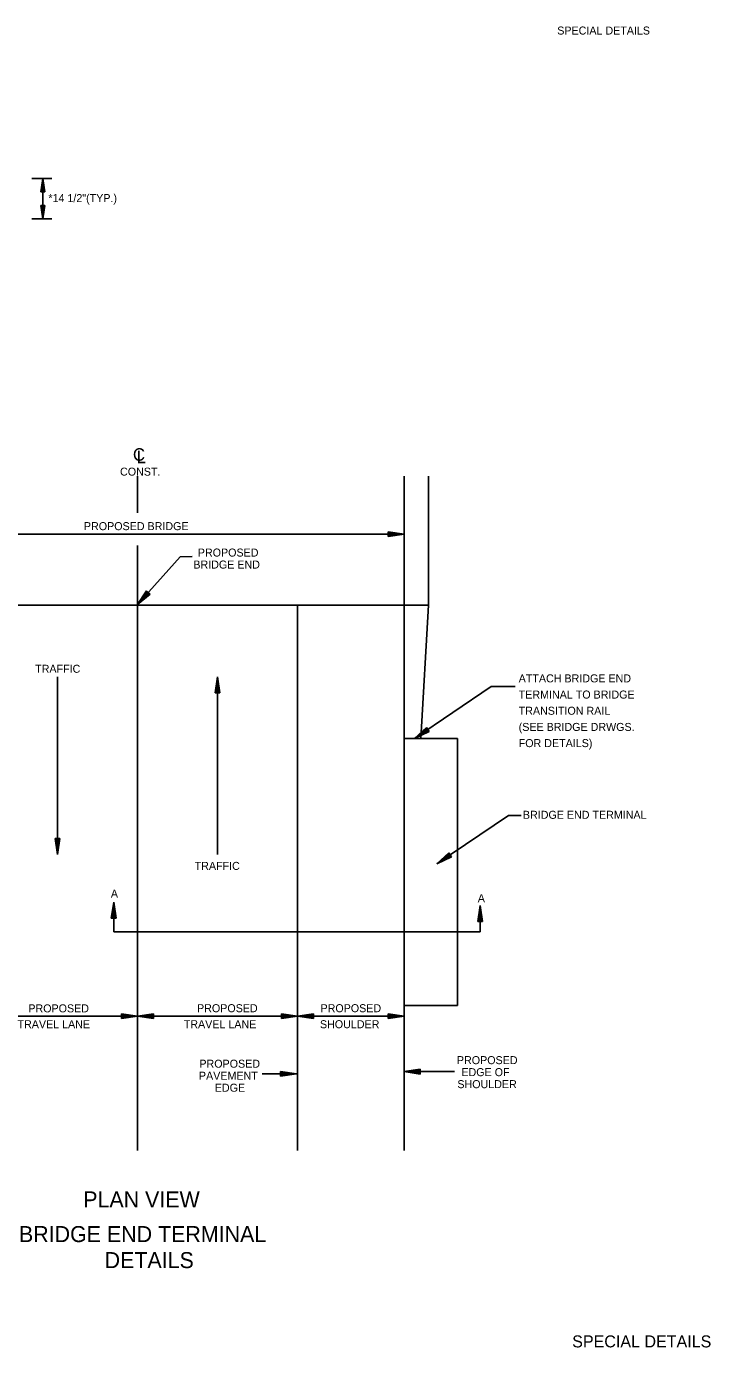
# Model space of a CAD drawing. Extents: x 1373918 to 1374069, y 381000 to 381245.
# Drawn here: x 1374017.6 to 1374068.9, y 381000 to 381099 of the extents above; entities that cross this region are included whole.
import ezdxf

# ---------------------------------------------------------------- set-up
doc = ezdxf.new("R2010")
doc.units = 0
for name, color, linetype in [('Default', 7, 'Continuous'), ('G-ANNO-TEXT', 7, 'Continuous'), ('R_Draft', 7, 'Continuous')]:
    doc.layers.add(name, color=color, linetype=linetype)

msp = doc.modelspace()

# ---------------------------------------------------------------- linework, layer by layer
at = {"layer": 'Default'}
for p, q in [((1374018.003, 381087.644), (1374019.497, 381087.644)), ((1374018.671, 381086.645), (1374018.821, 381087.645)), ((1374018.696, 381086.645), (1374018.821, 381087.48)), ((1374018.724, 381086.645), (1374018.821, 381087.307)), ((1374018.749, 381086.645), (1374018.821, 381087.14)), ((1374018.774, 381086.645), (1374018.821, 381086.97)), ((1374018.971, 381086.645), (1374018.821, 381087.645)), ((1374018.946, 381086.645), (1374018.821, 381087.48)), ((1374018.921, 381086.645), (1374018.821, 381087.307)), ((1374018.896, 381086.645), (1374018.821, 381087.14)), ((1374018.871, 381086.645), (1374018.821, 381086.97)), ((1374018.822, 381087.644), (1374018.822, 381084.623)), ((1374018.671, 381086.645), (1374018.971, 381086.645)), ((1374018.799, 381086.645), (1374018.821, 381086.805)), ((1374018.846, 381086.645), (1374018.821, 381086.805)), ((1374018.671, 381085.622), (1374018.821, 381084.622)), ((1374018.971, 381085.622), (1374018.671, 381085.622)), ((1374018.696, 381085.622), (1374018.821, 381084.79)), ((1374018.724, 381085.622), (1374018.821, 381084.962)), ((1374018.749, 381085.622), (1374018.821, 381085.127)), ((1374018.774, 381085.622), (1374018.821, 381085.297)), ((1374018.799, 381085.622), (1374018.821, 381085.465)), ((1374018.971, 381085.622), (1374018.821, 381084.622)), ((1374018.871, 381085.622), (1374018.821, 381085.297)), ((1374018.921, 381085.622), (1374018.821, 381084.962)), ((1374018.946, 381085.622), (1374018.821, 381084.79)), ((1374018.896, 381085.622), (1374018.821, 381085.127)), ((1374018.846, 381085.622), (1374018.821, 381085.465)), ((1374018.003, 381084.622), (1374019.497, 381084.622)), ((1374025.924, 381065.347), (1374025.924, 381062.586)), ((1374045.924, 381065.347), (1374045.924, 381055.667)), ((1374047.757, 381065.347), (1374047.757, 381055.667)), ((1374013.007, 381060.99), (1374045.924, 381060.99)), ((1374044.724, 381061.17), (1374045.924, 381060.99)), ((1374044.724, 381061.17), (1374044.724, 381060.81)), ((1374044.724, 381061.14), (1374045.724, 381060.99)), ((1374044.724, 381061.109), (1374045.517, 381060.99)), ((1374044.724, 381061.079), (1374045.317, 381060.99)), ((1374044.724, 381061.048), (1374045.114, 381060.99)), ((1374044.724, 381061.018), (1374044.914, 381060.99)), ((1374044.724, 381060.81), (1374045.924, 381060.99)), ((1374044.724, 381060.931), (1374045.114, 381060.99)), ((1374044.724, 381060.871), (1374045.517, 381060.99)), ((1374044.724, 381060.84), (1374045.724, 381060.99)), ((1374044.724, 381060.901), (1374045.317, 381060.99)), ((1374044.724, 381060.962), (1374044.914, 381060.99)), ((1374025.924, 381060.131), (1374025.924, 381014.792)), ((1374025.936, 381055.724), (1374029.124, 381059.302)), ((1374029.124, 381059.302), (1374030.028, 381059.304)), ((1374026.6, 381056.74), (1374025.936, 381055.724)), ((1374026.869, 381056.5), (1374025.936, 381055.724)), ((1374026.622, 381056.72), (1374026.069, 381055.874)), ((1374026.846, 381056.52), (1374026.069, 381055.874)), ((1374026.645, 381056.699), (1374026.207, 381056.028)), ((1374026.823, 381056.541), (1374026.207, 381056.028)), ((1374026.668, 381056.679), (1374026.34, 381056.177)), ((1374026.801, 381056.56), (1374026.34, 381056.177)), ((1374026.69, 381056.659), (1374026.475, 381056.329)), ((1374026.778, 381056.581), (1374026.475, 381056.329)), ((1374026.869, 381056.5), (1374026.6, 381056.74)), ((1374026.713, 381056.639), (1374026.608, 381056.478)), ((1374026.755, 381056.601), (1374026.608, 381056.478)), ((1374013.338, 381055.667), (1374047.757, 381055.667)), ((1374037.924, 381055.667), (1374037.924, 381014.792)), ((1374045.924, 381055.667), (1374045.924, 381045.667)), ((1374047.174, 381045.667), (1374047.757, 381055.667)), ((1374019.924, 381050.285), (1374019.924, 381036.974)), ((1374031.744, 381049.085), (1374031.924, 381050.285)), ((1374031.774, 381049.085), (1374031.924, 381050.085)), ((1374031.805, 381049.085), (1374031.924, 381049.878)), ((1374031.835, 381049.085), (1374031.924, 381049.678)), ((1374031.866, 381049.085), (1374031.924, 381049.475)), ((1374031.924, 381050.285), (1374031.924, 381036.974)), ((1374032.104, 381049.085), (1374031.924, 381050.285)), ((1374032.074, 381049.085), (1374031.924, 381050.085)), ((1374032.043, 381049.085), (1374031.924, 381049.878)), ((1374032.013, 381049.085), (1374031.924, 381049.678)), ((1374031.983, 381049.085), (1374031.924, 381049.475)), ((1374046.706, 381045.679), (1374052.457, 381049.578)), ((1374052.457, 381049.578), (1374054.266, 381049.578)), ((1374031.744, 381049.085), (1374032.104, 381049.085)), ((1374031.896, 381049.085), (1374031.924, 381049.275)), ((1374031.952, 381049.085), (1374031.924, 381049.275)), ((1374047.598, 381046.501), (1374046.706, 381045.679)), ((1374047.615, 381046.477), (1374046.872, 381045.791)), ((1374047.632, 381046.451), (1374047.043, 381045.907)), ((1374047.649, 381046.426), (1374047.208, 381046.019)), ((1374047.666, 381046.401), (1374047.376, 381046.134)), ((1374047.683, 381046.376), (1374047.542, 381046.246)), ((1374047.8, 381046.203), (1374047.598, 381046.501)), ((1374045.921, 381045.667), (1374045.921, 381025.667)), ((1374045.924, 381045.884), (1374045.924, 381014.792)), ((1374045.924, 381045.667), (1374049.928, 381045.667)), ((1374047.8, 381046.203), (1374046.706, 381045.679)), ((1374047.783, 381046.228), (1374046.872, 381045.791)), ((1374047.766, 381046.254), (1374047.043, 381045.907)), ((1374047.749, 381046.278), (1374047.208, 381046.019)), ((1374047.732, 381046.304), (1374047.376, 381046.134)), ((1374047.715, 381046.329), (1374047.542, 381046.246)), ((1374049.928, 381045.667), (1374049.928, 381025.667)), ((1374048.389, 381036.283), (1374053.75, 381039.902)), ((1374053.75, 381039.902), (1374054.696, 381039.909)), ((1374019.744, 381038.174), (1374019.924, 381036.974)), ((1374020.104, 381038.174), (1374019.744, 381038.174)), ((1374019.774, 381038.174), (1374019.924, 381037.174)), ((1374019.805, 381038.174), (1374019.924, 381037.381)), ((1374019.835, 381038.174), (1374019.924, 381037.581)), ((1374019.865, 381038.174), (1374019.924, 381037.784)), ((1374019.896, 381038.174), (1374019.924, 381037.984)), ((1374020.104, 381038.174), (1374019.924, 381036.974)), ((1374019.982, 381038.174), (1374019.924, 381037.784)), ((1374020.043, 381038.174), (1374019.924, 381037.381)), ((1374020.074, 381038.174), (1374019.924, 381037.174)), ((1374020.013, 381038.174), (1374019.924, 381037.581)), ((1374019.952, 381038.174), (1374019.924, 381037.984)), ((1374049.283, 381037.104), (1374048.389, 381036.283)), ((1374049.484, 381036.805), (1374048.389, 381036.283)), ((1374049.3, 381037.079), (1374048.555, 381036.395)), ((1374049.468, 381036.83), (1374048.555, 381036.395)), ((1374049.317, 381037.053), (1374048.726, 381036.511)), ((1374049.45, 381036.855), (1374048.726, 381036.511)), ((1374049.334, 381037.029), (1374048.892, 381036.622)), ((1374049.434, 381036.88), (1374048.892, 381036.622)), ((1374049.351, 381037.003), (1374049.06, 381036.736)), ((1374049.416, 381036.906), (1374049.06, 381036.736)), ((1374049.368, 381036.978), (1374049.226, 381036.848)), ((1374049.399, 381036.931), (1374049.226, 381036.848)), ((1374049.484, 381036.805), (1374049.283, 381037.104)), ((1374023.965, 381032.205), (1374024.145, 381033.405)), ((1374023.995, 381032.205), (1374024.145, 381033.205)), ((1374024.026, 381032.205), (1374024.145, 381032.998)), ((1374024.056, 381032.205), (1374024.145, 381032.798)), ((1374024.087, 381032.205), (1374024.145, 381032.595)), ((1374024.145, 381031.179), (1374024.145, 381033.405)), ((1374024.325, 381032.205), (1374024.145, 381033.405)), ((1374024.295, 381032.205), (1374024.145, 381033.205)), ((1374024.264, 381032.205), (1374024.145, 381032.998)), ((1374024.234, 381032.205), (1374024.145, 381032.798)), ((1374024.204, 381032.205), (1374024.145, 381032.595)), ((1374051.45, 381031.951), (1374051.63, 381033.151)), ((1374051.48, 381031.951), (1374051.63, 381032.951)), ((1374051.511, 381031.951), (1374051.63, 381032.744)), ((1374051.541, 381031.951), (1374051.63, 381032.544)), ((1374051.63, 381031.179), (1374051.63, 381033.151)), ((1374051.81, 381031.951), (1374051.63, 381033.151)), ((1374051.78, 381031.951), (1374051.63, 381032.951)), ((1374051.749, 381031.951), (1374051.63, 381032.744)), ((1374051.719, 381031.951), (1374051.63, 381032.544)), ((1374023.965, 381032.205), (1374024.325, 381032.205)), ((1374024.117, 381032.205), (1374024.145, 381032.395)), ((1374024.173, 381032.205), (1374024.145, 381032.395)), ((1374051.45, 381031.951), (1374051.81, 381031.951)), ((1374051.572, 381031.951), (1374051.63, 381032.341)), ((1374051.602, 381031.951), (1374051.63, 381032.141)), ((1374051.689, 381031.951), (1374051.63, 381032.341)), ((1374051.658, 381031.951), (1374051.63, 381032.141)), ((1374024.145, 381031.179), (1374051.63, 381031.179)), ((1374045.924, 381025.667), (1374049.928, 381025.667)), ((1374015.061, 381024.856), (1374025.924, 381024.856)), ((1374024.724, 381025.036), (1374025.924, 381024.856)), ((1374024.724, 381025.036), (1374024.724, 381024.676)), ((1374024.724, 381025.006), (1374025.724, 381024.856)), ((1374024.724, 381024.975), (1374025.517, 381024.856)), ((1374024.724, 381024.945), (1374025.317, 381024.856)), ((1374024.724, 381024.914), (1374025.114, 381024.856)), ((1374024.724, 381024.884), (1374024.914, 381024.856)), ((1374024.724, 381024.676), (1374025.924, 381024.856)), ((1374024.724, 381024.797), (1374025.114, 381024.856)), ((1374024.724, 381024.737), (1374025.517, 381024.856)), ((1374024.724, 381024.706), (1374025.724, 381024.856)), ((1374024.724, 381024.767), (1374025.317, 381024.856)), ((1374024.724, 381024.828), (1374024.914, 381024.856)), ((1374027.124, 381025.036), (1374025.924, 381024.856)), ((1374027.124, 381024.676), (1374025.924, 381024.856)), ((1374025.924, 381024.856), (1374037.924, 381024.856)), ((1374027.124, 381025.006), (1374026.124, 381024.856)), ((1374027.124, 381024.706), (1374026.124, 381024.856)), ((1374027.124, 381024.975), (1374026.331, 381024.856)), ((1374027.124, 381024.737), (1374026.331, 381024.856)), ((1374027.124, 381024.945), (1374026.531, 381024.856)), ((1374027.124, 381024.767), (1374026.531, 381024.856)), ((1374027.124, 381024.915), (1374026.734, 381024.856)), ((1374027.124, 381024.798), (1374026.734, 381024.856)), ((1374027.124, 381024.884), (1374026.934, 381024.856)), ((1374027.124, 381024.828), (1374026.934, 381024.856)), ((1374027.124, 381024.676), (1374027.124, 381025.036)), ((1374036.724, 381025.036), (1374037.924, 381024.856)), ((1374036.724, 381025.036), (1374036.724, 381024.676)), ((1374036.724, 381025.006), (1374037.724, 381024.856)), ((1374036.724, 381024.975), (1374037.517, 381024.856)), ((1374036.724, 381024.945), (1374037.317, 381024.856)), ((1374036.724, 381024.914), (1374037.114, 381024.856)), ((1374036.724, 381024.884), (1374036.914, 381024.856)), ((1374036.724, 381024.676), (1374037.924, 381024.856)), ((1374036.724, 381024.797), (1374037.114, 381024.856)), ((1374036.724, 381024.737), (1374037.517, 381024.856)), ((1374036.724, 381024.706), (1374037.724, 381024.856)), ((1374036.724, 381024.767), (1374037.317, 381024.856)), ((1374036.724, 381024.828), (1374036.914, 381024.856)), ((1374039.124, 381025.036), (1374037.924, 381024.856)), ((1374037.924, 381024.856), (1374045.924, 381024.856)), ((1374039.124, 381024.676), (1374037.924, 381024.856)), ((1374039.124, 381025.006), (1374038.124, 381024.856)), ((1374039.124, 381024.706), (1374038.124, 381024.856)), ((1374039.124, 381024.975), (1374038.331, 381024.856)), ((1374039.124, 381024.737), (1374038.331, 381024.856)), ((1374039.124, 381024.945), (1374038.531, 381024.856)), ((1374039.124, 381024.767), (1374038.531, 381024.856)), ((1374039.124, 381024.915), (1374038.734, 381024.856)), ((1374039.124, 381024.798), (1374038.734, 381024.856)), ((1374039.124, 381024.884), (1374038.934, 381024.856)), ((1374039.124, 381024.828), (1374038.934, 381024.856)), ((1374039.124, 381024.676), (1374039.124, 381025.036)), ((1374044.724, 381025.036), (1374045.924, 381024.856)), ((1374044.724, 381025.036), (1374044.724, 381024.676)), ((1374044.724, 381025.006), (1374045.724, 381024.856)), ((1374044.724, 381024.975), (1374045.517, 381024.856)), ((1374044.724, 381024.945), (1374045.317, 381024.856)), ((1374044.724, 381024.914), (1374045.114, 381024.856)), ((1374044.724, 381024.884), (1374044.914, 381024.856)), ((1374044.724, 381024.676), (1374045.924, 381024.856)), ((1374044.724, 381024.797), (1374045.114, 381024.856)), ((1374044.724, 381024.737), (1374045.517, 381024.856)), ((1374044.724, 381024.706), (1374045.724, 381024.856)), ((1374044.724, 381024.767), (1374045.317, 381024.856)), ((1374044.724, 381024.828), (1374044.914, 381024.856)), ((1374036.653, 381020.724), (1374037.853, 381020.544)), ((1374036.653, 381020.724), (1374036.653, 381020.364)), ((1374036.653, 381020.694), (1374037.653, 381020.544)), ((1374036.653, 381020.663), (1374037.446, 381020.544)), ((1374036.653, 381020.633), (1374037.246, 381020.544)), ((1374047.124, 381020.883), (1374045.924, 381020.703)), ((1374049.71, 381020.703), (1374045.924, 381020.703)), ((1374047.124, 381020.523), (1374045.924, 381020.703)), ((1374047.124, 381020.853), (1374046.124, 381020.703)), ((1374047.124, 381020.553), (1374046.124, 381020.703)), ((1374047.124, 381020.822), (1374046.331, 381020.703)), ((1374047.124, 381020.584), (1374046.331, 381020.703)), ((1374047.124, 381020.792), (1374046.531, 381020.703)), ((1374047.124, 381020.614), (1374046.531, 381020.703)), ((1374047.124, 381020.762), (1374046.734, 381020.703)), ((1374047.124, 381020.645), (1374046.734, 381020.703)), ((1374047.124, 381020.731), (1374046.934, 381020.703)), ((1374047.124, 381020.675), (1374046.934, 381020.703)), ((1374047.124, 381020.523), (1374047.124, 381020.883)), ((1374035.268, 381020.544), (1374037.853, 381020.544)), ((1374036.653, 381020.602), (1374037.043, 381020.544)), ((1374036.653, 381020.572), (1374036.843, 381020.544)), ((1374036.653, 381020.364), (1374037.853, 381020.544)), ((1374036.653, 381020.485), (1374037.043, 381020.544)), ((1374036.653, 381020.425), (1374037.446, 381020.544)), ((1374036.653, 381020.394), (1374037.653, 381020.544)), ((1374036.653, 381020.455), (1374037.246, 381020.544)), ((1374036.653, 381020.516), (1374036.843, 381020.544))]:
    msp.add_line(p, q, dxfattribs=at)

# ---------------------------------------------------------------- texts
for s, height, p in [('*14 1/2"(TYP.)', 0.6, (1374019.246, 381085.88)), ('CONST.', 0.6, (1374024.621, 381065.376)), ('PROPOSED BRIDGE', 0.6, (1374021.911, 381061.29)), ('PROPOSED', 0.6, (1374030.454, 381059.31)), ('BRIDGE END', 0.6, (1374030.118, 381058.41)), ('TRAFFIC', 0.6, (1374018.253, 381050.599)), ('ATTACH BRIDGE END', 0.6, (1374054.519, 381049.879)), ('TERMINAL TO BRIDGE', 0.6, (1374054.519, 381048.666)), ('TRANSITION RAIL', 0.6, (1374054.519, 381047.453)), ('(SEE BRIDGE DRWGS.', 0.6, (1374054.519, 381046.24)), ('FOR DETAILS)', 0.6, (1374054.519, 381045.027)), ('BRIDGE END TERMINAL', 0.6, (1374054.835, 381039.653)), ('TRAFFIC', 0.6, (1374030.217, 381035.823)), ('A', 0.6, (1374023.932, 381033.742)), ('A', 0.6, (1374051.45, 381033.403)), ('PROPOSED', 0.6, (1374017.743, 381025.144)), ('PROPOSED', 0.6, (1374030.395, 381025.156)), ('PROPOSED', 0.6, (1374039.655, 381025.156)), ('TRAVEL LANE', 0.6, (1374016.931, 381023.956)), ('TRAVEL LANE', 0.6, (1374029.4, 381023.956)), ('SHOULDER', 0.6, (1374039.613, 381023.956)), ('PROPOSED', 0.6, (1374049.885, 381021.263)), ('PAVEMENT', 0.6, (1374030.537, 381020.096)), ('PROPOSED', 0.6, (1374030.571, 381020.996)), ('EDGE OF', 0.6, (1374050.22, 381020.363)), ('EDGE', 0.6, (1374031.726, 381019.196)), ('SHOULDER', 0.6, (1374049.918, 381019.463)), ('PLAN VIEW', 1.2, (1374021.859, 381010.525)), ('BRIDGE END TERMINAL', 1.2, (1374017.04, 381007.926)), ('DETAILS', 1.2, (1374023.465, 381005.976))]:
    msp.add_text(s, height=height, dxfattribs=at).set_placement(p)
at = {"layer": 'G-ANNO-TEXT'}
for height, p in [(0.6, (1374057.41, 381098.439)), (0.9, (1374058.531, 381000.031))]:
    msp.add_text('SPECIAL DETAILS', height=height, dxfattribs=at).set_placement(p)
at = {"layer": 'R_Draft'}
for s, p in [('C', (1374025.587, 381066.493)), ('L', (1374025.87, 381066.31))]:
    msp.add_text(s, height=0.938, dxfattribs=at).set_placement(p)

doc.saveas('drawing.dxf')
